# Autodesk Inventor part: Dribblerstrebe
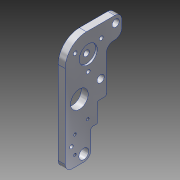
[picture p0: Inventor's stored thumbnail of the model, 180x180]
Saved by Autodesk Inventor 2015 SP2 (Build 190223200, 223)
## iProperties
Created: 2015-08
Part Number: Dribblerstrebe
Material: Aluminium 6061
Document SubType Name: Modeling
Designer: ryll
Mass: 14.8896 g
Surface Area: 38.6459 cm^2
Volume: 5.51466 cm^3
Density: 2.7 g/cm^3
Appearance: Aluminium - flach
Author: ryll
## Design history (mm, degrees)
sketch "Skizze1" dims "d5" = 16
  geometry: L1 (-8, 28)-(-8, -4); L2 (0, 74.748)-(0, -18.091) reference; L3 (-17.548, 0)-(31.891, 0) reference; L4 (-8, 28)-(-8, 47); L5 (4, 59)-(20, 59); L6 (15.25, 47)-(15.25, 22); L7 (-8, -4)-(2.5, -4); L8 (15.25, 22)-(10, 22); L9 (6.5, 0)-(6.5, 11); L10 (24, 55)-(24, 47); L11 (24, 47)-(15.25, 47); L12 (10, 22)-(10, 11); L13 (10, 11)-(6.5, 11); C1 r 11 at (5, 47.468); C2 r 8.5 at (5, 47.468); C3 r 0.5 at (0, 28); C4 r 0.5 at (5, 47.468); C5 r 0.5 at (12, 32); C6 r 0.5 at (2.5, 0); C7 r 0.5 at (20.5, 55); A1 r 12 centre (4, 47) between (4, 59) and (-8, 47); A2 r 4 centre (2.5, 0) between (2.5, -4) and (6.5, 0); A3 r 4 centre (20, 55) between (24, 55) and (20, 59); 2 further points
  constraints: 22 end point, 10 centre point, 6 point on circle, 6 tangent, 4 coincident, 4 parallel, 3 vertical, 2 horizontal, 2 perpendicular, 2 point on line, 1 horizontal alignment, 2 other
  dimensions: "d2" = 22 diameter of C1; "d3" = 17 diameter of C2; "d6" = 20.1 distance of C1.centre point (0, 28); "d7" = 28 distance from line of L3 point (0, 28); "d12" = 1 diameter of C3; "d13" = 1 diameter of C4; "d54" = 12 radius of A1; "d57" = 5 distance from line of L2 C2.centre; "d86" = 1 diameter of C5; "d96" = 12 horizontal distance of C5.centre point (0, 28); "d108" = 1 diameter of C6; "d112" = 10.5 distance from line of L1 C6.centre; "d118" = 14.5 distance between parallel lines of L1 L9; "d150" = 22 distance between parallel lines of L3 L8; "d152" = 63 distance between parallel lines of L7 L5; "d153" = 4 radius of A3; "d154" = 32 distance between parallel lines of L10 L4; "d155" = 47 distance between parallel lines of L11 L3; "d156" = 5.25 distance of L8.end L6.end; "d158" = 1 diameter of C7; "d168" = 4 distance from line of L5 C7.centre; "d169" = 28.5 distance from line of C7.centre L4; "d171" = 10 distance from line of L8 C5.centre; "d172" = 11 distance of L8.end L12.end; "d173" = 3.5 distance of L12.end L9.end
extrude "Extrusion1" new body sketch "Skizze1" stored distance "d10" = 4; taper "d11" = 0 deg
sketch "Skizze4"
  geometry: C1 r 0.5 at (28, 0) reference; 2 further points
  constraints: 1 coincident
hole "Bohrung3" sketch "Skizze4" at (28, 0) diameter "d32" = 10; stored, may be unused: countersink angle "d36" = 90 deg, drill point angle "d38" = 118 deg; dims "d33" = 6, "d34" = 10.5, "d35" = 1, "d37" = 8
sketch "Skizze2"
  geometry: L1 (-16.6, 0)-(71.6, 0) reference; L2 (47.468, 5)-(51.718, 12.361); L3 (47.468, 5)-(55.968, 5); C1 r 0.5 at (47.468, 5) reference; C2 r 0.5 at (47.468, 5) reference; A1 r 8.5 centre (47.468, 5) between (51.718, 12.361) and (55.968, 5); 1 further point
  constraints: 4 end point, 2 point on circle, 1 centre point, 1 coincident, 1 horizontal
  dimensions: "d14" = 17 diameter of A1; "d46" = 60 deg angle of L2 L3
hole "Bohrung1" sketch "Skizze2" at (51.718, 12.361) diameter "d15" = 2.1; stored, may be unused: countersink angle "d19" = 90 deg, drill point angle "d21" = 118 deg; dims "d16" = 6, "d17" = 4, "d18" = 2, "d20" = 8
pattern_circular "Runde Anordnung1" dims angle "d23" = 360 deg
sketch "Skizze5"
  geometry: C1 r 0.5 at (-47.468, 5) reference; 2 further points
  constraints: 1 coincident
hole "Bohrung4" sketch "Skizze5" at (-47.468, 5) diameter "d39" = 3.2; stored, may be unused: countersink angle "d43" = 90 deg, drill point angle "d45" = 118 deg; dims "d40" = 6, "d41" = 10.2, "d42" = 1, "d44" = 8
sketch "Skizze6"
  geometry: C1 r 0.5 at (0, 2.5) reference; 1 further point
  constraints: 1 coincident
hole "Bohrung5" sketch "Skizze6" at (0, 2.5) diameter "d47" = 5.6; stored, may be unused: countersink angle "d51" = 90 deg, drill point angle "d53" = 118 deg; dims "d48" = 6, "d49" = 10.2, "d50" = 1, "d52" = 8
sketch "Skizze9"
  geometry: C1 r 0.5 at (32, 12) reference; 2 further points
  constraints: 1 coincident
hole "Bohrung8" sketch "Skizze9" at (32, 12) diameter "d87" = 4.1; stored, may be unused: countersink angle "d91" = 90 deg, drill point angle "d93" = 118 deg; dims "d88" = 6, "d89" = 6, "d90" = 1.5, "d92" = 8
mirror "Spiegeln1"
workplane "Arbeitsebene1"
  workpoint "Arbeitspunkt1"
fillet "Rundung1" dims "d120" = 4
sketch "Skizze11"
  geometry: L1 (-16.6, 0)-(71.6, 0) reference; L2 (0, 30.4)-(0, -14.4) reference; L3 (12, -2.5)-(2, -2.5); L4 (7, -2.5)-(7, 0); L5 (-4, 2.5)-(-4, -4) reference; 3 further points
  constraints: 4 end point, 2 coincident, 1 horizontal, 1 midpoint, 1 perpendicular, 1 point on line
  dimensions: "d121" = 10 distance of L3.start L3.end; "d122" = 2.5 distance between parallel lines of L1 L3; "d132" = 11 distance between parallel lines of L4 L5
hole "Bohrung9" sketch "Skizze11" at (12, -2.5), (2, -2.5) diameter "d124" = 1.567; stored, may be unused: countersink angle "d128" = 90 deg, drill point angle "d130" = 118 deg; dims "d125" = 4, "d126" = 4, "d127" = 2, "d129" = 6.3
sketch "Skizze12"
  geometry: L1 (12, -2.5)-(2, -2.5); L2 (7, -2.5)-(7, -4.5); C1 r 0.784 at (12, -2.5) reference; C2 r 0.784 at (2, -2.5) reference; 1 further point
  constraints: 4 end point, 1 horizontal, 1 midpoint, 1 vertical
  dimensions: "d140" = 2 distance from line of L2.end L1
hole "Bohrung10" sketch "Skizze12" at (7, -4.5) diameter "d133" = 2; stored, may be unused: countersink angle "d137" = 90 deg, drill point angle "d139" = 118 deg; dims "d134" = 4, "d135" = 4, "d136" = 2, "d138" = 6.3
sketch "Skizze13"
  geometry: L1 (0, 2.5)-(15.844, 4.727); L2 (0, 2.5)-(16, 2.5); C1 r 2.8 at (0, 2.5) reference; A1 r 16 centre (0, 2.5) between (15.844, 4.727) and (16, 2.5); 1 further point
  constraints: 4 end point, 2 point on circle, 1 centre point, 1 coincident, 1 horizontal
  dimensions: "d141" = 32 diameter of A1; "d149" = 8 deg angle of L1 L2
hole "Bohrung11" sketch "Skizze13" at (15.844, 4.727) diameter "d142" = 1.567; stored, may be unused: countersink angle "d146" = 90 deg, drill point angle "d148" = 118 deg; dims "d143" = 4, "d144" = 4, "d145" = 2, "d147" = 6.3
fillet "Fillet2" dims "d157" = 1
sketch "Skizze14"
  geometry: C1 r 0.5 at (-55, 20.5) reference; C2 r 0.5 at (-55, 20.5) reference; 2 further points
  constraints: 1 coincident
hole "Bohrung12" sketch "Skizze14" at (-55, 20.5) diameter "d161" = 4.1; stored, may be unused: countersink angle "d165" = 90 deg, drill point angle "d167" = 118 deg; dims "d162" = 6, "d163" = 4, "d164" = 2, "d166" = 8
fillet "Rundung3" dims "d170" = 4
node "Volumenkörper1"
workaxis "Arbeitsachse1"
other parameters: "d109" = 8, "d110" = 14.5
